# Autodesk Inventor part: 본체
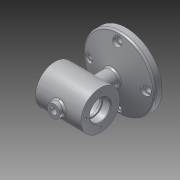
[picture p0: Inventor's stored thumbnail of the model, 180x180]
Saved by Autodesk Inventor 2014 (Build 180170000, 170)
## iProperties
Created: 2018-12
Part Number: 본체
Material: 알루미늄 6061
Document SubType Name: Modeling
Designer: 601-21
Density: 2.71 g/cm^3
Appearance: 알루미늄 - 평지
Mass: 687.571 g
Surface Area: 554.176 cm^2
Volume: 253.716 cm^3
Author: 601-21
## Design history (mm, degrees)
sketch "스케치1"
  geometry: L1 (0, 0)-(-35, 0); L2 (0, 0)-(35, 0); L3 (-35, 0)-(-35, 16); L4 (-35, 16)-(-23.3, 16); L5 (-23, 15.7)-(-23, 14); L6 (-23, 14)-(-20, 14); L7 (-20, 14)-(-20, 22); L8 (-17, 25)-(17, 25); L9 (20, 22)-(20, 14); L10 (20, 14)-(23, 14); L11 (23, 14)-(23, 15.7); L12 (23.3, 16)-(35, 16); L13 (35, 16)-(35, 0); L14 (-35, 16)-(-35, 30); L15 (-35, 30)-(35, 30); L16 (35, 30)-(35, 16); A1 r 3 centre (-17, 22) between (-17, 25) and (-20, 22); A2 r 3 centre (17, 22) between (20, 22) and (17, 25); A3 r 0.3 centre (-23.3, 15.7) between (-23, 15.7) and (-23.3, 16); A4 r 0.3 centre (23.3, 15.7) between (23.3, 16) and (23, 15.7); 4 further points
  constraints: 32 end point, 9 parallel, 9 point on line, 8 point on circle, 8 tangent, 4 centre point, 4 perpendicular, 2 collinear, 2 equal radius, 1 horizontal
  dimensions: "d0" = 35 distance of L1.start L1.end; "d1" = 35 distance of L1.start L2.end; "d2" = 70 distance between parallel lines of L16 L14; "d3" = 12 distance of L3.end point (-23, 16); "d4" = 12 distance of point (23, 16) L12.end; "d5" = 40 distance of point (-20, 25) point (20, 25); "d6" = 3 distance of L5.end L6.end; "d7" = 60 diameter of L15 L1; "d8" = 32 diameter of L4 L1; "d9" = 28 diameter of L6 L1; "d10" = 50 diameter of L8 L1; "d11" = 28 diameter of L10 L2; "d12" = 32 diameter of L12 L2; "d13" = 3 radius of A1; "d14" = 0.3 radius of A3
revolve "회전1" sketch "스케치1" stored, may be unused: angle "d15" = 90 deg
node "작업 평면1"
sketch "스케치2"
  geometry: C1 r 55 at (0, 0); 1 further point
  constraints: 1 centre point, 1 coincident
  dimensions: "d17" = 110 diameter of C1
extrude "돌출1" join sketch "스케치2" distance "d18" = 11; taper "d19" = 0 deg
sketch "스케치3"
  geometry: C1 r 55 at (0, 0) reference; C2 r 12 at (0, 0)
  constraints: 1 centre point, 1 coincident
  dimensions: "d20" = 24 diameter of C2
extrude "돌출2" join sketch "스케치3" stored distance "d21" = 0; taper "d22" = 0 deg
sketch "스케치4"
  geometry: C1 r 55 at (0, 0) reference; C2 r 55 at (0, 0)
  constraints: 1 centre point, 1 coincident, 1 concentric
extrude "돌출3" join sketch "스케치4" distance "d23" = 50; taper "d24" = -75 deg
node "작업 평면2"
sketch "스케치5"
  geometry: L1 (35, -30)-(35, 30) reference; L2 (-35, -30)-(-35, 30) reference; C1 r 10 at (0, 0); 2 further points
  constraints: 1 centre point, 1 coincident, 1 other
  dimensions: "d26" = 20 diameter of C1
extrude "돌출4" join sketch "스케치5" stored distance "d27" = 50; taper "d28" = 0 deg
sketch "스케치6"
  geometry: C1 r 10 at (0, 0) reference; C2 r 5 at (0, 0)
  constraints: 1 centre point, 1 coincident
  dimensions: "d29" = 10 diameter of C2
extrude "돌출5" cut sketch "스케치6" stored distance "d30" = 50; taper "d31" = 0 deg
sketch "스케치7" dims "d32" = 88
  geometry: C1 r 55 at (0, 0) reference; C2 r 4.5 at (-44, 0); 1 further point
  constraints: 1 centre point, 1 coincident, 1 horizontal alignment, 2 other
  dimensions: "d33" = 9 diameter of C2
extrude "돌출6" cut sketch "스케치7" distance "d34" = 10; taper "d35" = 0 deg
node "작업 평면3"
sketch "스케치8"
  geometry: C1 r 4.5 at (-44, 0) reference; C2 r 7 at (-44, 0); 1 further point
  constraints: 1 centre point, 1 coincident
  dimensions: "d37" = 14 diameter of C2
extrude "돌출7" cut sketch "스케치8" distance "d38" = 10; taper "d39" = 0 deg
sketch "스케치9" dims "d43" = 46
  geometry: C1 r 30 at (0, 0) reference; 2 further points
  constraints: 1 coincident, 1 vertical alignment, 2 other
hole "구멍1" sketch "스케치9" at (0, -23) diameter "d44" = 3.242; stored, may be unused: countersink angle "d48" = 90 deg, drill point angle "d50" = 118 deg; dims "d45" = 8, "d46" = 4, "d47" = 2, "d49" = 10
fillet "모깎기1" dims "d54" = 3
chamfer "모따기1" distance "d55" = 1; stored, may be unused: second distance "d56" = 2, angle "d57" = 45 deg
chamfer "모따기2" distance "d58" = 1; stored, may be unused: second distance "d59" = 2, angle "d60" = 45 deg
node "작업 평면4"
sketch "스케치10"
  geometry: L1 (35, -30)-(-35, -30) reference; L2 (35, 30)-(35, -30) reference; L3 (24.887, -3.602)-(-24.887, -3.602); L4 (-24.887, -3.602)-(-24.887, 3.602); L5 (-24.887, 3.602)-(24.887, 3.602); L6 (24.887, 3.602)-(24.887, -3.602); L7 (24.887, -3.602)-(-24.887, 3.602); L8 (-24.887, -3.602)-(24.887, 3.602); 4 further points
  constraints: 4 end point, 2 coincident, 2 midpoint, 2 other
feature "엠보싱1" sketch "스케치10" dims "d14" = 0.3, "d61" = 0.5, "d62" = 0
node "솔리드1"
pattern_circular "원형 패턴1" dims angle "d41" = 360 deg
pattern_circular "원형 패턴2" dims angle "d52" = 360 deg
mirror "대칭1"
node "투영된 루프1"
node "투영된 루프2"
other parameters: "d16" = 75, "d25" = -112
